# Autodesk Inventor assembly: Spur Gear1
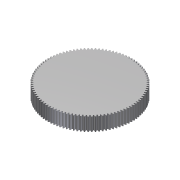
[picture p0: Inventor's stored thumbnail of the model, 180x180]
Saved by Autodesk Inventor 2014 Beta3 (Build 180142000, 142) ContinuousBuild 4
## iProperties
Created: 2011-01
Part Number: Spur Gear1
Document SubType Name: Assembly
Designer: Beta-8540w
Categories: <?xml version="1.0" encoding="UTF-16"?> <MemberInstance><Categories><FamilyTemplate/><ParamToTemplateMap><ParamToTemplate><ParamToTemplate CategoryParameter="//
ClientObjectVersion: 1
Author: Beta-8540w
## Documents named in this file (2)
- C:\Inventor 2014 Essentials\Assemblies\Chapter 09\Design Accelerators\Spur Gear c09-02.iam
- C:\Inventor 2014 Essentials\Assemblies\Chapter 09\Design Accelerators\Spur Gear c09-02.ipt
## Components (1 placed, 1 different names)
1. Spur Gear2:1
